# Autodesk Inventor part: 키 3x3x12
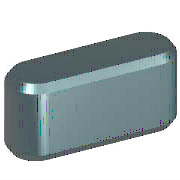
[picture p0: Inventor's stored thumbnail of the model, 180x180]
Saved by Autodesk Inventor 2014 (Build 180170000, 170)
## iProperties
Created: 2012-02
Part Number: 키 3x3x12
Material: 강철, 연강
Description: 키 및 해당 키홈
Document SubType Name: Modeling
Standard: KS B 1311
Designer: mduedu
Standards Organization: KS
Language: ko-KR
Size Designation: 3 x 3 x 12
Categories: <MemberInstance><Categories><Category DisplayName="샤프트 부품" InternalName="7f7aeb1f-a693-4053-b835-cee3144e0d98" Mnemonic="SHFT"><Category DisplayName="키" Interna
Density: 1 g/cm^3
Appearance: Yellow
IsCustomPart: 1
Author: mduedu
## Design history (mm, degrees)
sketch "스케치1"
  geometry: L1 (1.5, 1.5)-(10.5, 1.5); L2 (10.5, -1.5)-(1.5, -1.5); L3 (0, 9.4)-(0, -7.4) reference; L4 (-5, 0)-(30, 0) reference; L5 (12, 0)-(12, 7); A1 r 1.5 centre (1.5, 0) between (1.5, 1.5) and (1.5, -1.5); A2 r 1.5 centre (10.5, 0) between (10.5, -1.5) and (10.5, 1.5)
  constraints: 6 end point, 5 point on circle, 4 tangent, 3 point on line, 2 centre point, 1 horizontal, 1 parallel, 1 perpendicular
  dimensions: "d0" = 1.5 radius of A1 (= 0.5 x PB); "d13" = 1.5 radius of A2 (= 0.5 x PB); "d14" = 12 distance between parallel lines of L5 L3 (= NLG)
extrude "본체1" new body sketch "스케치1" taper "d3" = 0 deg; stored distance "d4" = 10
workplane "Work Plane3"
body "Solid1"
workplane "Work Plane1"
workplane "Work Plane2"
chamfer "모따기1" distance "d8" = 0.25 (= PHH); stored, may be unused: second distance "d9" = 0.25 (= PHH), angle "d15" = 45 deg
other parameters: "d1" = -1.8 (= -PNT), "d2" = 1.2 (= PH - PNT), "NLG" = 12 [user parameter; used in 3 equation terms], "PB" = 3 [user parameter; used in 2 equation terms], "PNT" = 1.8 [user parameter; used in 2 equation terms], "PH" = 3 [user parameter; used in 1 equation term], "PHH" = 0.25 [user parameter; used in 2 equation terms], "d10" = 0, "d16" = 0, "d17" = 0, "d18" = 0, "WDMIN" = 8 [user parameter], "PLB2" = 12 (= NLG) [user parameter], "PLB1" = 12 (= NLG) [user parameter], "RR" = 0.08 [user parameter], "PUEB" = 1.4 [user parameter]
